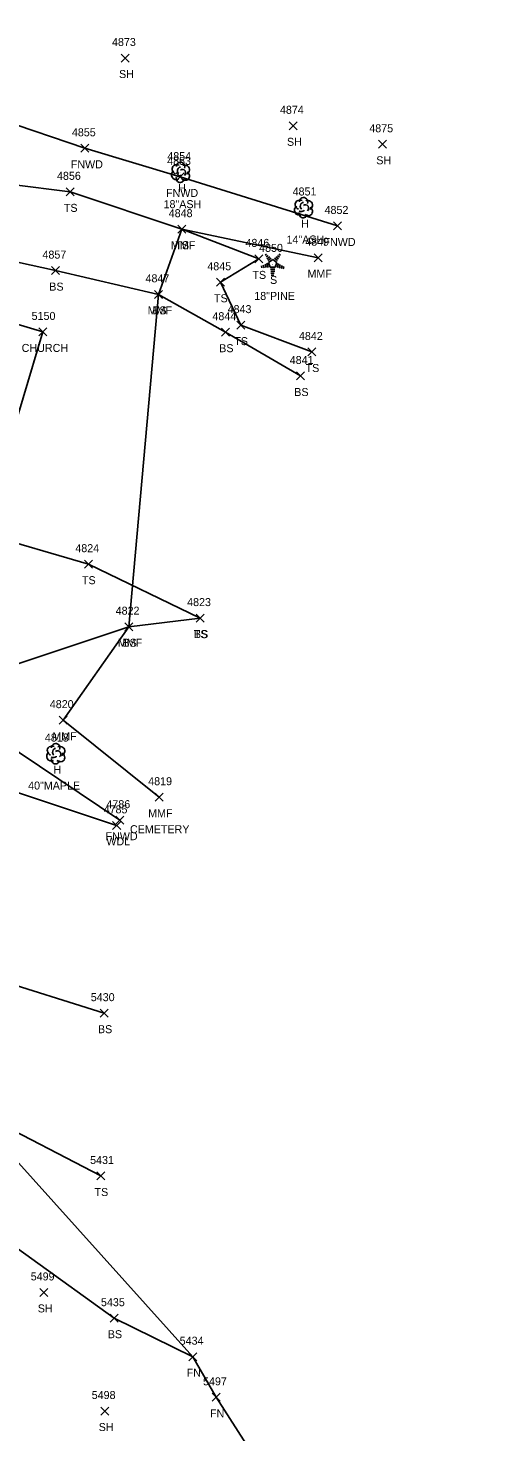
# Model space of a CAD drawing. Extents: x 1601151 to 1602912, y 499508 to 501770.
# Drawn here: x 1601596 to 1601711.1, y 500954.3 to 501305.1 of the extents above; entities that cross this region are included whole.
import ezdxf

# ---------------------------------------------------------------- set-up
doc = ezdxf.new("R2010")
doc.units = 0
for name, color, linetype in [('L_A', 7, 'Continuous'), ('L_C', 7, 'Continuous'), ('L_I', 7, 'Continuous'), ('L_TIC', 7, 'Continuous'), ('LAWA', 7, 'Continuous'), ('LBC', 7, 'Continuous'), ('LDEFAULT', 7, 'Continuous'), ('LELB', 7, 'Continuous'), ('LFNC', 7, 'Continuous'), ('LTC', 7, 'Continuous'), ('LTD', 7, 'Continuous')]:
    doc.layers.add(name, color=color, linetype=linetype)

msp = doc.modelspace()

# ---------------------------------------------------------------- linework, layer by layer
at = {"layer": 'L_TIC'}
for points in [[(1601619.26, 501296.58), (1601621.26, 501298.58)], [(1601621.26, 501296.58), (1601619.26, 501298.58)], [(1601661.2, 501279.64), (1601663.2, 501281.64)], [(1601663.2, 501279.64), (1601661.2, 501281.64)], [(1601609.24, 501274.02), (1601611.24, 501276.02)], [(1601611.24, 501274.02), (1601609.24, 501276.02)], [(1601683.51, 501275.02), (1601685.51, 501277.02)], [(1601685.51, 501275.02), (1601683.51, 501277.02)], [(1601633.03, 501266.87), (1601635.03, 501268.87)], [(1601635.03, 501266.87), (1601633.03, 501268.87)], [(1601605.58, 501263.14), (1601607.58, 501265.14)], [(1601607.58, 501263.14), (1601605.58, 501265.14)], [(1601633.42, 501253.81), (1601635.42, 501255.81)], [(1601635.42, 501253.81), (1601633.42, 501255.81)], [(1601633.42, 501253.81), (1601635.42, 501255.81)], [(1601635.42, 501253.81), (1601633.42, 501255.81)], [(1601672.34, 501254.62), (1601674.34, 501256.62)], [(1601674.34, 501254.62), (1601672.34, 501256.62)], [(1601652.65, 501246.39), (1601654.65, 501248.39)], [(1601654.65, 501246.39), (1601652.65, 501248.39)], [(1601667.52, 501246.68), (1601669.52, 501248.68)], [(1601669.52, 501246.68), (1601667.52, 501248.68)], [(1601601.89, 501243.46), (1601603.89, 501245.46)], [(1601603.89, 501243.46), (1601601.89, 501245.46)], [(1601643.06, 501240.55), (1601645.06, 501242.55)], [(1601645.06, 501240.55), (1601643.06, 501242.55)], [(1601627.63, 501237.53), (1601629.63, 501239.53)], [(1601629.63, 501237.53), (1601627.63, 501239.53)], [(1601627.63, 501237.53), (1601629.63, 501239.53)], [(1601629.63, 501237.53), (1601627.63, 501239.53)], [(1601598.7, 501228.14), (1601600.7, 501230.14)], [(1601600.7, 501228.14), (1601598.7, 501230.14)], [(1601644.33, 501228.07), (1601646.33, 501230.07)], [(1601646.33, 501228.07), (1601644.33, 501230.07)], [(1601648.13, 501229.84), (1601650.13, 501231.84)], [(1601650.13, 501229.84), (1601648.13, 501231.84)], [(1601665.94, 501223.13), (1601667.94, 501225.13)], [(1601667.94, 501223.13), (1601665.94, 501225.13)], [(1601663.07, 501217.13), (1601665.07, 501219.13)], [(1601665.07, 501217.13), (1601663.07, 501219.13)], [(1601610.1, 501170.11), (1601612.1, 501172.11)], [(1601612.1, 501170.11), (1601610.1, 501172.11)], [(1601620.17, 501154.49), (1601622.17, 501156.49)], [(1601622.17, 501154.49), (1601620.17, 501156.49)], [(1601620.17, 501154.49), (1601622.17, 501156.49)], [(1601622.17, 501154.49), (1601620.17, 501156.49)], [(1601638.02, 501156.64), (1601640.02, 501158.64)], [(1601640.02, 501156.64), (1601638.02, 501158.64)], [(1601638.02, 501156.64), (1601640.02, 501158.64)], [(1601640.02, 501156.64), (1601638.02, 501158.64)], [(1601603.8, 501131.14), (1601605.8, 501133.14)], [(1601605.8, 501131.14), (1601603.8, 501133.14)], [(1601627.74, 501111.89), (1601629.74, 501113.89)], [(1601629.74, 501111.89), (1601627.74, 501113.89)], [(1601617.92, 501106.15), (1601619.92, 501108.15)], [(1601619.92, 501106.15), (1601617.92, 501108.15)], [(1601617.16, 501104.86), (1601619.16, 501106.86)], [(1601619.16, 501104.86), (1601617.16, 501106.86)], [(1601614.05, 501057.93), (1601616.05, 501059.93)], [(1601616.05, 501057.93), (1601614.05, 501059.93)], [(1601613.22, 501017.25), (1601615.22, 501019.25)], [(1601615.22, 501017.25), (1601613.22, 501019.25)], [(1601598.97, 500988.16), (1601600.97, 500990.16)], [(1601600.97, 500988.16), (1601598.97, 500990.16)], [(1601616.5, 500981.72), (1601618.5, 500983.72)], [(1601618.5, 500981.72), (1601616.5, 500983.72)], [(1601636.16, 500972.1), (1601638.16, 500974.1)], [(1601638.16, 500972.1), (1601636.16, 500974.1)], [(1601641.99, 500961.95), (1601643.99, 500963.95)], [(1601643.99, 500961.95), (1601641.99, 500963.95)], [(1601641.99, 500961.95), (1601643.99, 500963.95)], [(1601643.99, 500961.95), (1601641.99, 500963.95)], [(1601614.19, 500958.53), (1601616.19, 500960.53)], [(1601616.19, 500958.53), (1601614.19, 500960.53)]]:
    msp.add_lwpolyline(points, dxfattribs=at)
at = {"layer": 'LAWA'}
msp.add_lwpolyline([(1601618.16, 501105.86), (1601588.54, 501115.65), (1601565.4, 501138.09), (1601542.31, 501150.13), (1601528.87, 501161.11), (1601492.28, 501187.38), (1601492.54, 501173.85), (1601490.69, 501172.33), (1601496.33, 501148.54)], dxfattribs=at)
at = {"layer": 'LBC'}
msp.add_lwpolyline([(1601545.26, 501209.35), (1601546.86, 501215.25), (1601553.32, 501236.6), (1601555.17, 501242.38), (1601599.7, 501229.14), (1601589.86, 501196.22)], dxfattribs=at)
at = {"layer": 'LDEFAULT'}
msp.add_lwpolyline([(1601628.74, 501112.89), (1601604.8, 501132.14), (1601621.17, 501155.49), (1601628.63, 501238.53), (1601634.42, 501254.81), (1601668.52, 501247.68)], dxfattribs=at)
at = {"layer": 'LELB'}
for points in [[(1601666.94, 501224.13), (1601649.13, 501230.84), (1601644.06, 501241.55), (1601653.65, 501247.39), (1601634.42, 501254.81), (1601606.58, 501264.14), (1601562.75, 501269.66), (1601530.94, 501289.24), (1601514.29, 501293.7), (1601485.76, 501300.21)], [(1601664.07, 501218.13), (1601645.33, 501229.07), (1601628.63, 501238.53), (1601602.89, 501244.46), (1601558.05, 501254.32), (1601511.72, 501260.36)], [(1601480.04, 501230.08), (1601481.02, 501220.84), (1601484.49, 501191.95), (1601487.17, 501184.79), (1601490.69, 501172.33), (1601502.32, 501150.22), (1601523.31, 501131.22), (1601544.43, 501107.88), (1601586.9, 501067.79), (1601615.05, 501058.93)], [(1601639.02, 501157.64), (1601611.1, 501171.11), (1601584.8, 501178.76), (1601542.46, 501192.22), (1601518, 501210.36), (1601503.08, 501230.36)], [(1601572.42, 501139.2), (1601621.17, 501155.49), (1601639.02, 501157.64)], [(1601614.22, 501018.25), (1601585.91, 501032.96), (1601552.42, 501068), (1601526.18, 501094.76)], [(1601617.5, 500982.72), (1601576.29, 501012.39), (1601548.69, 501057.95), (1601535.63, 501063.32)], [(1601617.5, 500982.72), (1601637.16, 500973.1)]]:
    msp.add_lwpolyline(points, dxfattribs=at)
at = {"layer": 'LFNC'}
for points in [[(1601673.34, 501255.62), (1601634.03, 501267.87), (1601610.24, 501275.02), (1601568, 501289.38), (1601516.13, 501305.06)], [(1601618.92, 501107.15), (1601588.69, 501127.51), (1601566.23, 501142.23), (1601531.27, 501164.59), (1601489.16, 501191.87), (1601499.35, 501229.93)], [(1601585.39, 501030.58), (1601637.16, 500973.1), (1601642.99, 500962.95)], [(1601711.12, 500852.81), (1601690.2, 500889.26), (1601642.99, 500962.95)]]:
    msp.add_lwpolyline(points, dxfattribs=at)
at = {"layer": 'LTC'}
for p, q in [((1601655.27, 501248.35), (1601655.62, 501248.61)), ((1601655.48, 501247.88), (1601656.01, 501248.27)), ((1601655.69, 501247.42), (1601656.39, 501247.93)), ((1601655.9, 501246.95), (1601656.77, 501247.59)), ((1601656.12, 501246.5), (1601657.13, 501247.23)), ((1601657.13, 501247.23), (1601658.13, 501246.51)), ((1601657.55, 501247.55), (1601658.36, 501246.96)), ((1601657.92, 501247.89), (1601658.6, 501247.4)), ((1601658.29, 501248.24), (1601658.84, 501247.84)), ((1601658.67, 501248.59), (1601659.09, 501248.29)), ((1601654.3, 501245.63), (1601654.45, 501245.16)), ((1601654.76, 501245.85), (1601654.97, 501245.19)), ((1601655.21, 501246.06), (1601655.48, 501245.23)), ((1601655.67, 501246.28), (1601656, 501245.26)), ((1601656.12, 501246.5), (1601656.51, 501245.3)), ((1601657.74, 501245.3), (1601656.51, 501245.3)), ((1601657.7, 501244.8), (1601656.56, 501244.8)), ((1601657.62, 501244.3), (1601656.63, 501244.3)), ((1601657.53, 501243.8), (1601656.7, 501243.8)), ((1601658.13, 501246.51), (1601657.74, 501245.3)), ((1601658.57, 501246.24), (1601658.23, 501245.2)), ((1601659.01, 501245.99), (1601658.72, 501245.1)), ((1601659.46, 501245.74), (1601659.22, 501245.01)), ((1601659.9, 501245.49), (1601659.71, 501244.91)), ((1601657.45, 501243.3), (1601656.77, 501243.3))]:
    msp.add_line(p, q, dxfattribs=at)
at = {"layer": 'LTD'}
for p, q in [((1601634.07, 501269.06), (1601634.07, 501269.06)), ((1601634.07, 501269.06), (1601634.07, 501269.06)), ((1601664.79, 501260.23), (1601664.79, 501260.23)), ((1601664.79, 501260.23), (1601664.79, 501260.23)), ((1601602.92, 501123.8), (1601602.92, 501123.8)), ((1601602.92, 501123.8), (1601602.92, 501123.8))]:
    msp.add_line(p, q, dxfattribs=at)
for centre in [(1601634.12, 501270.5), (1601664.84, 501261.66), (1601602.96, 501125.24)]:
    msp.add_arc(centre, 1.05, 335.5272, 180.9563, dxfattribs=at)
for centre, major_axis, ratio, start_param, end_param in [((1601632.99, 501268.35), (0.58, -1.04), 0.959034, 3.141593, 6.283185), ((1601633.28, 501269.73), (1.21, -0.51), 0.895232, 1.570796, 4.712389), ((1601633.62, 501268.31), (-0.625, -0.083), 0.423636, 0, 3.141593), ((1601633.87, 501269.52), (-0.208, -0.792), 0.645439, 3.141593, 6.283185), ((1601634.57, 501268.9), (-0.5, 0.667), 0.989748, 3.141593, 6.283185), ((1601635.07, 501268.23), (-1.09, 0.79), 0.841452, 1.570796, 4.712389), ((1601635.12, 501269.65), (-1.14, -0.48), 0.949671, 1.570796, 4.712389), ((1601634.07, 501267.56), (0.26, 1.06), 0.942809, 1.570796, 4.712389), ((1601664, 501260.89), (1.21, -0.51), 0.895232, 1.570796, 4.712389), ((1601664.58, 501260.68), (-0.208, -0.792), 0.645439, 3.141593, 6.283185), ((1601665.83, 501260.81), (-1.14, -0.48), 0.949671, 1.570796, 4.712389), ((1601663.71, 501259.52), (0.58, -1.04), 0.959034, 3.141593, 6.283185), ((1601664.79, 501258.73), (0.26, 1.06), 0.942809, 1.570796, 4.712389), ((1601664.33, 501259.48), (-0.625, -0.083), 0.423636, 0, 3.141593), ((1601665.29, 501260.06), (-0.5, 0.667), 0.989748, 3.141593, 6.283185), ((1601665.79, 501259.39), (-1.09, 0.79), 0.841452, 1.570796, 4.712389), ((1601602.13, 501124.47), (1.21, -0.51), 0.895232, 1.570796, 4.712389), ((1601602.71, 501124.26), (-0.208, -0.792), 0.645439, 3.141593, 6.283185), ((1601603.42, 501123.64), (-0.5, 0.667), 0.989748, 3.141593, 6.283185), ((1601603.96, 501124.39), (-1.14, -0.48), 0.949671, 1.570796, 4.712389), ((1601601.83, 501123.09), (0.58, -1.04), 0.959034, 3.141593, 6.283185), ((1601602.92, 501122.3), (0.26, 1.06), 0.942809, 1.570796, 4.712389), ((1601602.46, 501123.05), (-0.625, -0.083), 0.423636, 0, 3.141593), ((1601603.92, 501122.97), (-1.09, 0.79), 0.841452, 1.570796, 4.712389)]:
    msp.add_ellipse(centre, major_axis=major_axis, ratio=ratio, start_param=start_param, end_param=end_param, dxfattribs=at)

# ---------------------------------------------------------------- texts
at = {"layer": 'L_A'}
for s, p in [('SH', (1601618.75, 501292.58)), ('SH', (1601660.69, 501275.64)), ('FNWD', (1601606.7, 501270.02)), ('SH', (1601683, 501271.02)), ('FNWD', (1601630.49, 501262.87)), ('H', (1601633.51, 501264.06)), ('TS', (1601604.98, 501259.14)), ('H', (1601664.22, 501255.23)), ('MMF', (1601631.71, 501249.81)), ('TS', (1601632.83, 501249.81)), ('FNWD', (1601669.81, 501250.62)), ('TS', (1601652.06, 501242.39)), ('MMF', (1601665.81, 501242.68)), ('BS', (1601601.33, 501239.46)), ('S', (1601656.46, 501241.14)), ('TS', (1601642.47, 501236.55)), ('MMF', (1601625.91, 501233.53)), ('BS', (1601627.07, 501233.53)), ('CHURCH', (1601594.44, 501224.14)), ('TS', (1601647.54, 501225.84)), ('BS', (1601643.77, 501224.07)), ('TS', (1601665.35, 501219.13)), ('BS', (1601662.51, 501213.13)), ('TS', (1601609.5, 501166.11)), ('MMF', (1601618.45, 501150.49)), ('BS', (1601619.61, 501150.49)), ('TS', (1601637.43, 501152.64)), ('BS', (1601637.46, 501152.64)), ('MMF', (1601602.09, 501127.14)), ('H', (1601602.35, 501118.8)), ('MMF', (1601626.02, 501107.89)), ('FNWD', (1601615.38, 501102.15)), ('WDL', (1601615.58, 501100.86)), ('BS', (1601613.49, 501053.93)), ('TS', (1601612.63, 501013.25)), ('SH', (1601598.46, 500984.16)), ('BS', (1601615.94, 500977.72)), ('FN', (1601635.64, 500968.1)), ('FN', (1601641.47, 500957.95)), ('FN', (1601641.47, 500957.95)), ('SH', (1601613.68, 500954.53))]:
    msp.add_text(s, height=2, dxfattribs=at).set_placement(p)
at = {"layer": 'L_C'}
for s, p in [('18"ASH', (1601629.87, 501260.06)), ('14"ASH', (1601660.58, 501251.23)), ('18"PINE', (1601652.52, 501237.14)), ('40"MAPLE', (1601596.05, 501114.8)), ('CEMETERY', (1601621.48, 501103.89))]:
    msp.add_text(s, height=2, dxfattribs=at).set_placement(p)
at = {"layer": 'L_I'}
for s, p in [('4873', (1601617, 501300.58)), ('4874', (1601658.94, 501283.64)), ('4855', (1601606.98, 501278.02)), ('4875', (1601681.25, 501279.02)), ('4853', (1601630.77, 501270.87)), ('4854', (1601630.81, 501272.06)), ('4856', (1601603.26, 501267.14)), ('4851', (1601662.1, 501263.23)), ('4848', (1601631.16, 501257.81)), ('4848', (1601631.16, 501257.81)), ('4852', (1601670.08, 501258.62)), ('4846', (1601650.33, 501250.39)), ('4850', (1601653.73, 501249.14)), ('4849', (1601665.26, 501250.68)), ('4857', (1601599.63, 501247.46)), ('4845', (1601640.8, 501244.55)), ('4847', (1601625.37, 501241.53)), ('4847', (1601625.37, 501241.53)), ('5150', (1601596.92, 501232.14)), ('4844', (1601642.07, 501232.07)), ('4843', (1601645.87, 501233.84)), ('4842', (1601663.68, 501227.13)), ('4841', (1601661.38, 501221.13)), ('4824', (1601607.84, 501174.11)), ('4822', (1601617.91, 501158.49)), ('4822', (1601617.91, 501158.49)), ('4823', (1601635.76, 501160.64)), ('4823', (1601635.76, 501160.64)), ('4820', (1601601.46, 501135.14)), ('4818', (1601600.23, 501126.8)), ('4819', (1601626.04, 501115.89)), ('4785', (1601614.9, 501108.86)), ('4786', (1601615.6, 501110.15)), ('5430', (1601611.7, 501061.93)), ('5431', (1601611.53, 501021.25)), ('5499', (1601596.7, 500992.16)), ('5435', (1601614.24, 500985.72)), ('5434', (1601633.9, 500976.1)), ('5497', (1601639.73, 500965.95)), ('5497', (1601639.73, 500965.95)), ('5498', (1601611.93, 500962.53))]:
    msp.add_text(s, height=2, dxfattribs=at).set_placement(p)
at = {"layer": 'LTC'}
msp.add_text('.', height=1.04, rotation=270, dxfattribs=at).set_placement((1601657.02, 501246.25))

doc.saveas('drawing.dxf')
